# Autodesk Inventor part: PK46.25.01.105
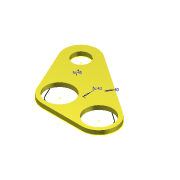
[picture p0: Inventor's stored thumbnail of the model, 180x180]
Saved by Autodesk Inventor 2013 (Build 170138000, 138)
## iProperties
Created: 2005-04
Part Number: PK46.25.01.105
Material: Steel, Mild
Document SubType Name: Modeling
Designer: salex
Manufacturer: Standard
Standards Organization: Custom
Density: 7.86 g/cm^3
Mass: 9147.22 g
Surface Area: 2089.08 cm^2
Volume: 1163.77 cm^3
Author: salex
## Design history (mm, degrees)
sketch "Эскиз1"
  geometry: L1 (-63.901, 332.782)-(298.904, 86.921); L2 (240, -105)-(0, -105); L3 (-95.464, -43.723)-(-210.918, 208.359); C1 r 82 at (0, 0); C2 r 82 at (240, 0); C3 r 50 at (-120, 250); A1 r 100 centre (-120, 250) between (-63.901, 332.782) and (-210.918, 208.359); A2 r 105 centre (0, 0) between (-95.464, -43.723) and (0, -105); A3 r 105 centre (240, 0) between (240, -105) and (298.904, 86.921)
  constraints: 6 centre point, 6 end point, 6 point on circle, 6 tangent, 3 coincident, 2 equal radius, 1 other
  dimensions: "d0" = 240 distance of C2.centre C1.centre; "d1" = 0 vertical distance of C2.centre C1.centre; "d2" = 164 diameter of C1; "d3" = 100 diameter of C3; "d4" = 105 radius of A2; "d5" = 100 radius of A1; "d6" = 250 vertical distance of C1.centre C3.centre; "d7" = 120 horizontal distance of C1.centre C3.centre
extrude "Выдавливание1" new body sketch "Эскиз1" distance "d8" = 25; taper "d9" = 0 deg
sketch "Sketch3"
  geometry: L1 (-298.904, 86.921)-(63.901, 332.782) reference; L2 (0, -105)-(-240, -105) reference; L3 (210.918, 208.359)-(95.464, -43.723) reference; L4 (-40, 78.704)-(-200, 78.704); L5 (174.551, 225.016)-(59.097, -27.066); L6 (0, -65)-(-240, -65); L7 (-276.464, 53.809)-(86.341, 299.669); L8 (127.234, 121.704)-(-176.274, 121.704); C1 r 50 at (120, 250) reference; A1 r 100 centre (120, 250) between (210.918, 208.359) and (63.901, 332.782) reference; A2 r 105 centre (-240, 0) between (-298.904, 86.921) and (-240, -105) reference; A3 r 105 centre (0, 0) between (0, -105) and (95.464, -43.723) reference; A4 r 60 centre (120, 250) between (174.551, 225.016) and (86.341, 299.669); A5 r 65 centre (0, 0) between (0, -65) and (59.097, -27.066); A6 r 65 centre (-240, 0) between (-276.464, 53.809) and (-240, -65); A7 r 95 centre (120, 250) between (25.368, 258.35) and (143.881, 158.05)
  constraints: 10 end point, 8 point on circle, 4 centre point, 4 point on line, 2 parallel, 5 other
  dimensions: "d18" = 40 distance between parallel lines of L1 L7; "d19" = 45 radial gap between concentric circles of C1 A7 (computed from d18); "d20" = 43 distance between parallel lines of L8 L4 (computed from d19)
body "Solid1"
